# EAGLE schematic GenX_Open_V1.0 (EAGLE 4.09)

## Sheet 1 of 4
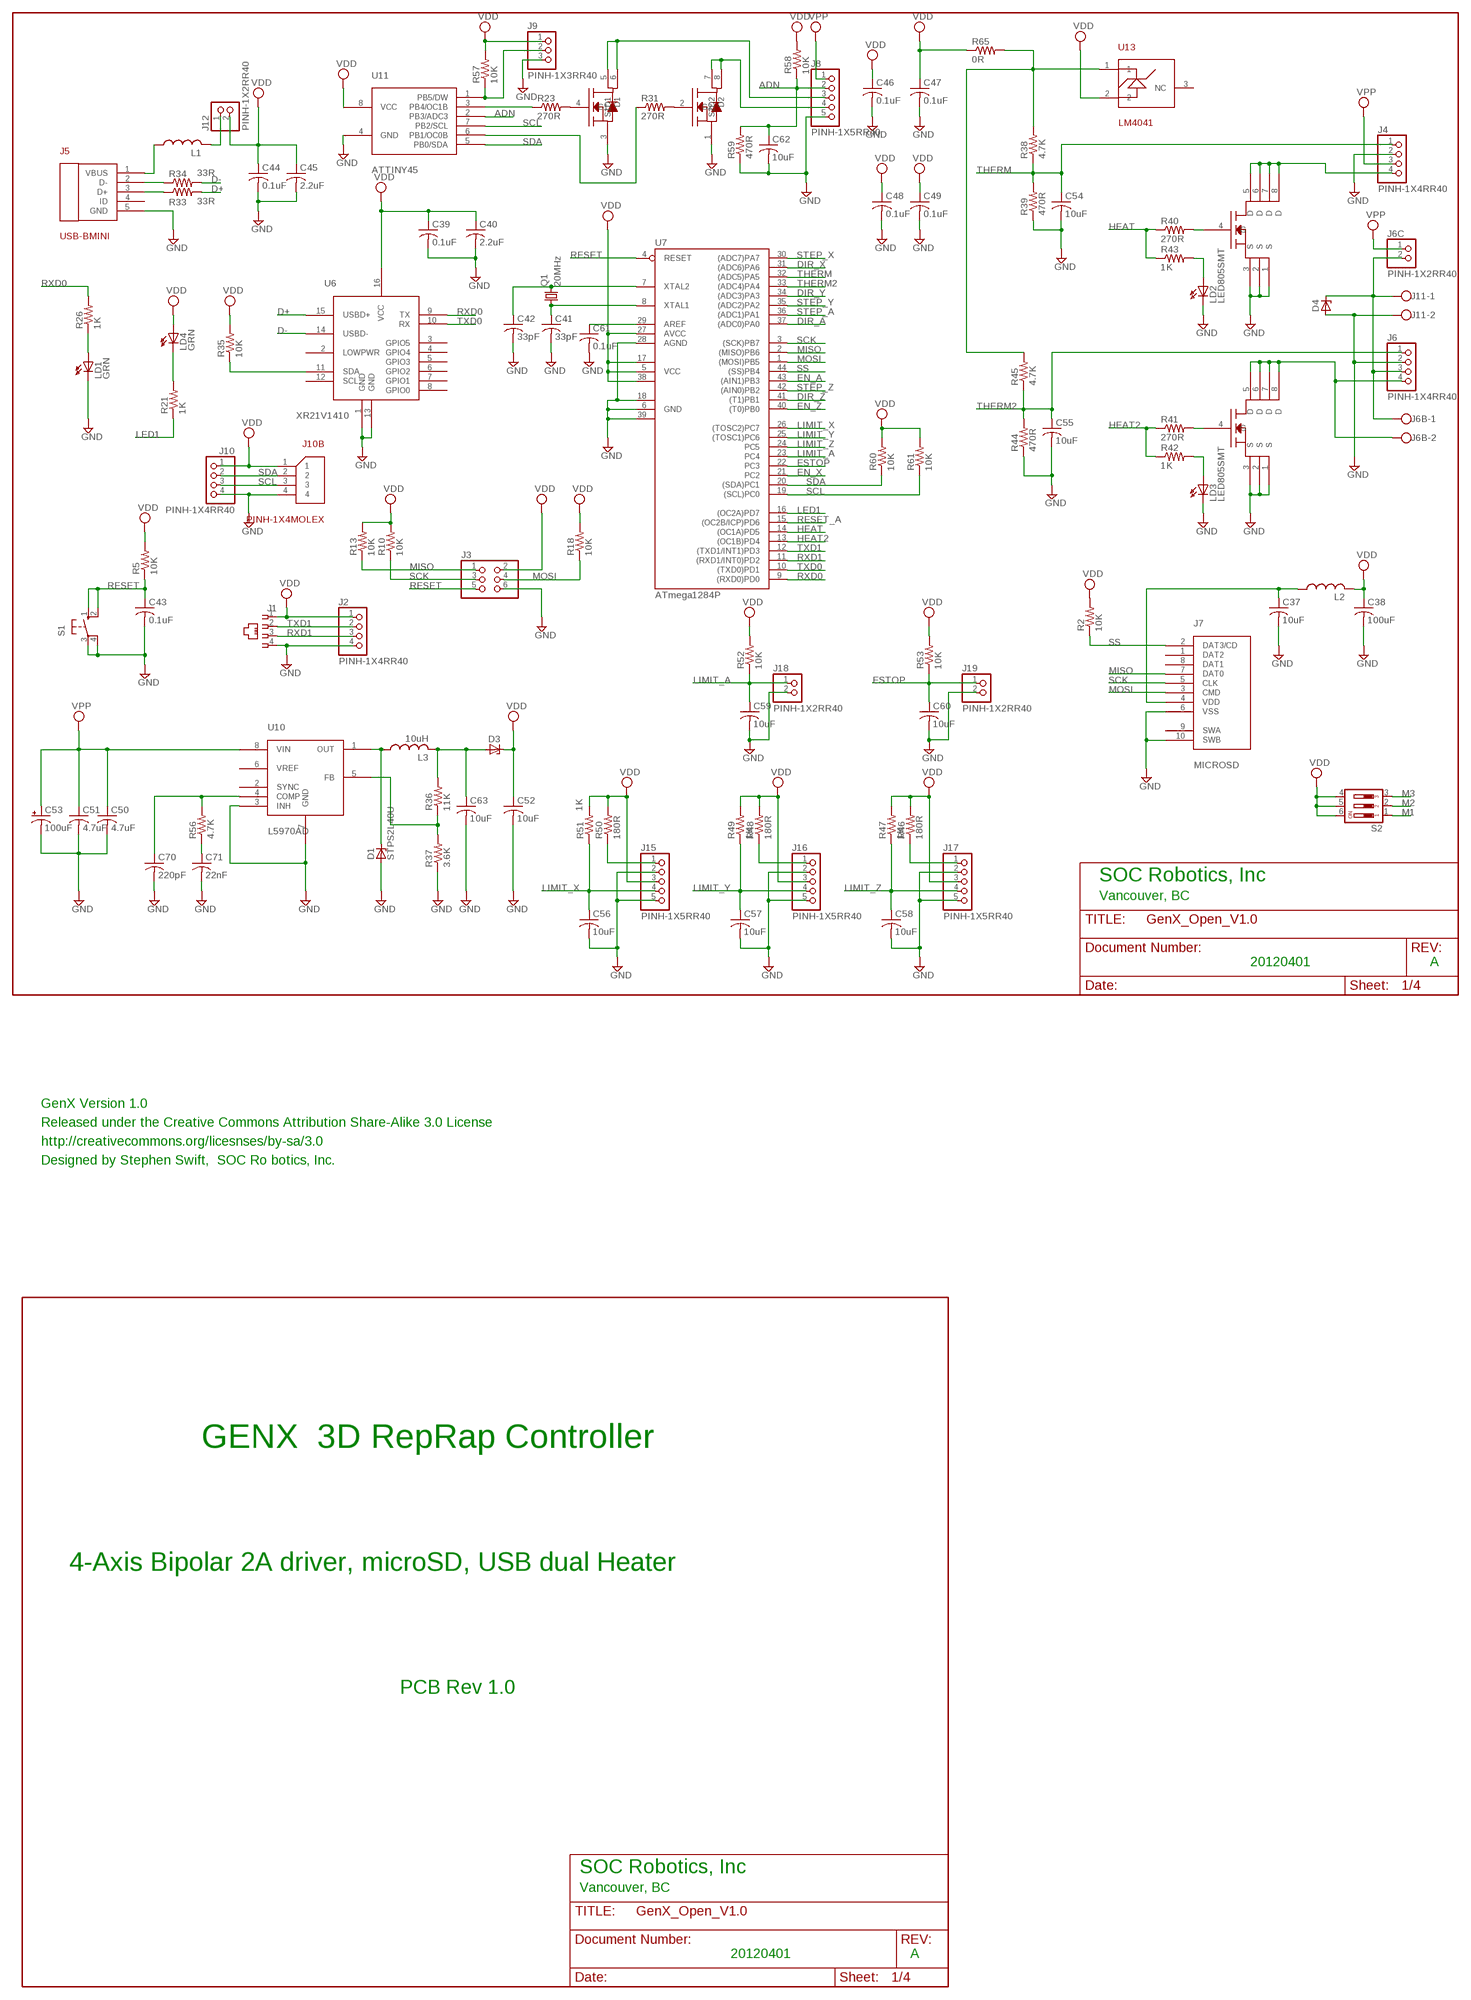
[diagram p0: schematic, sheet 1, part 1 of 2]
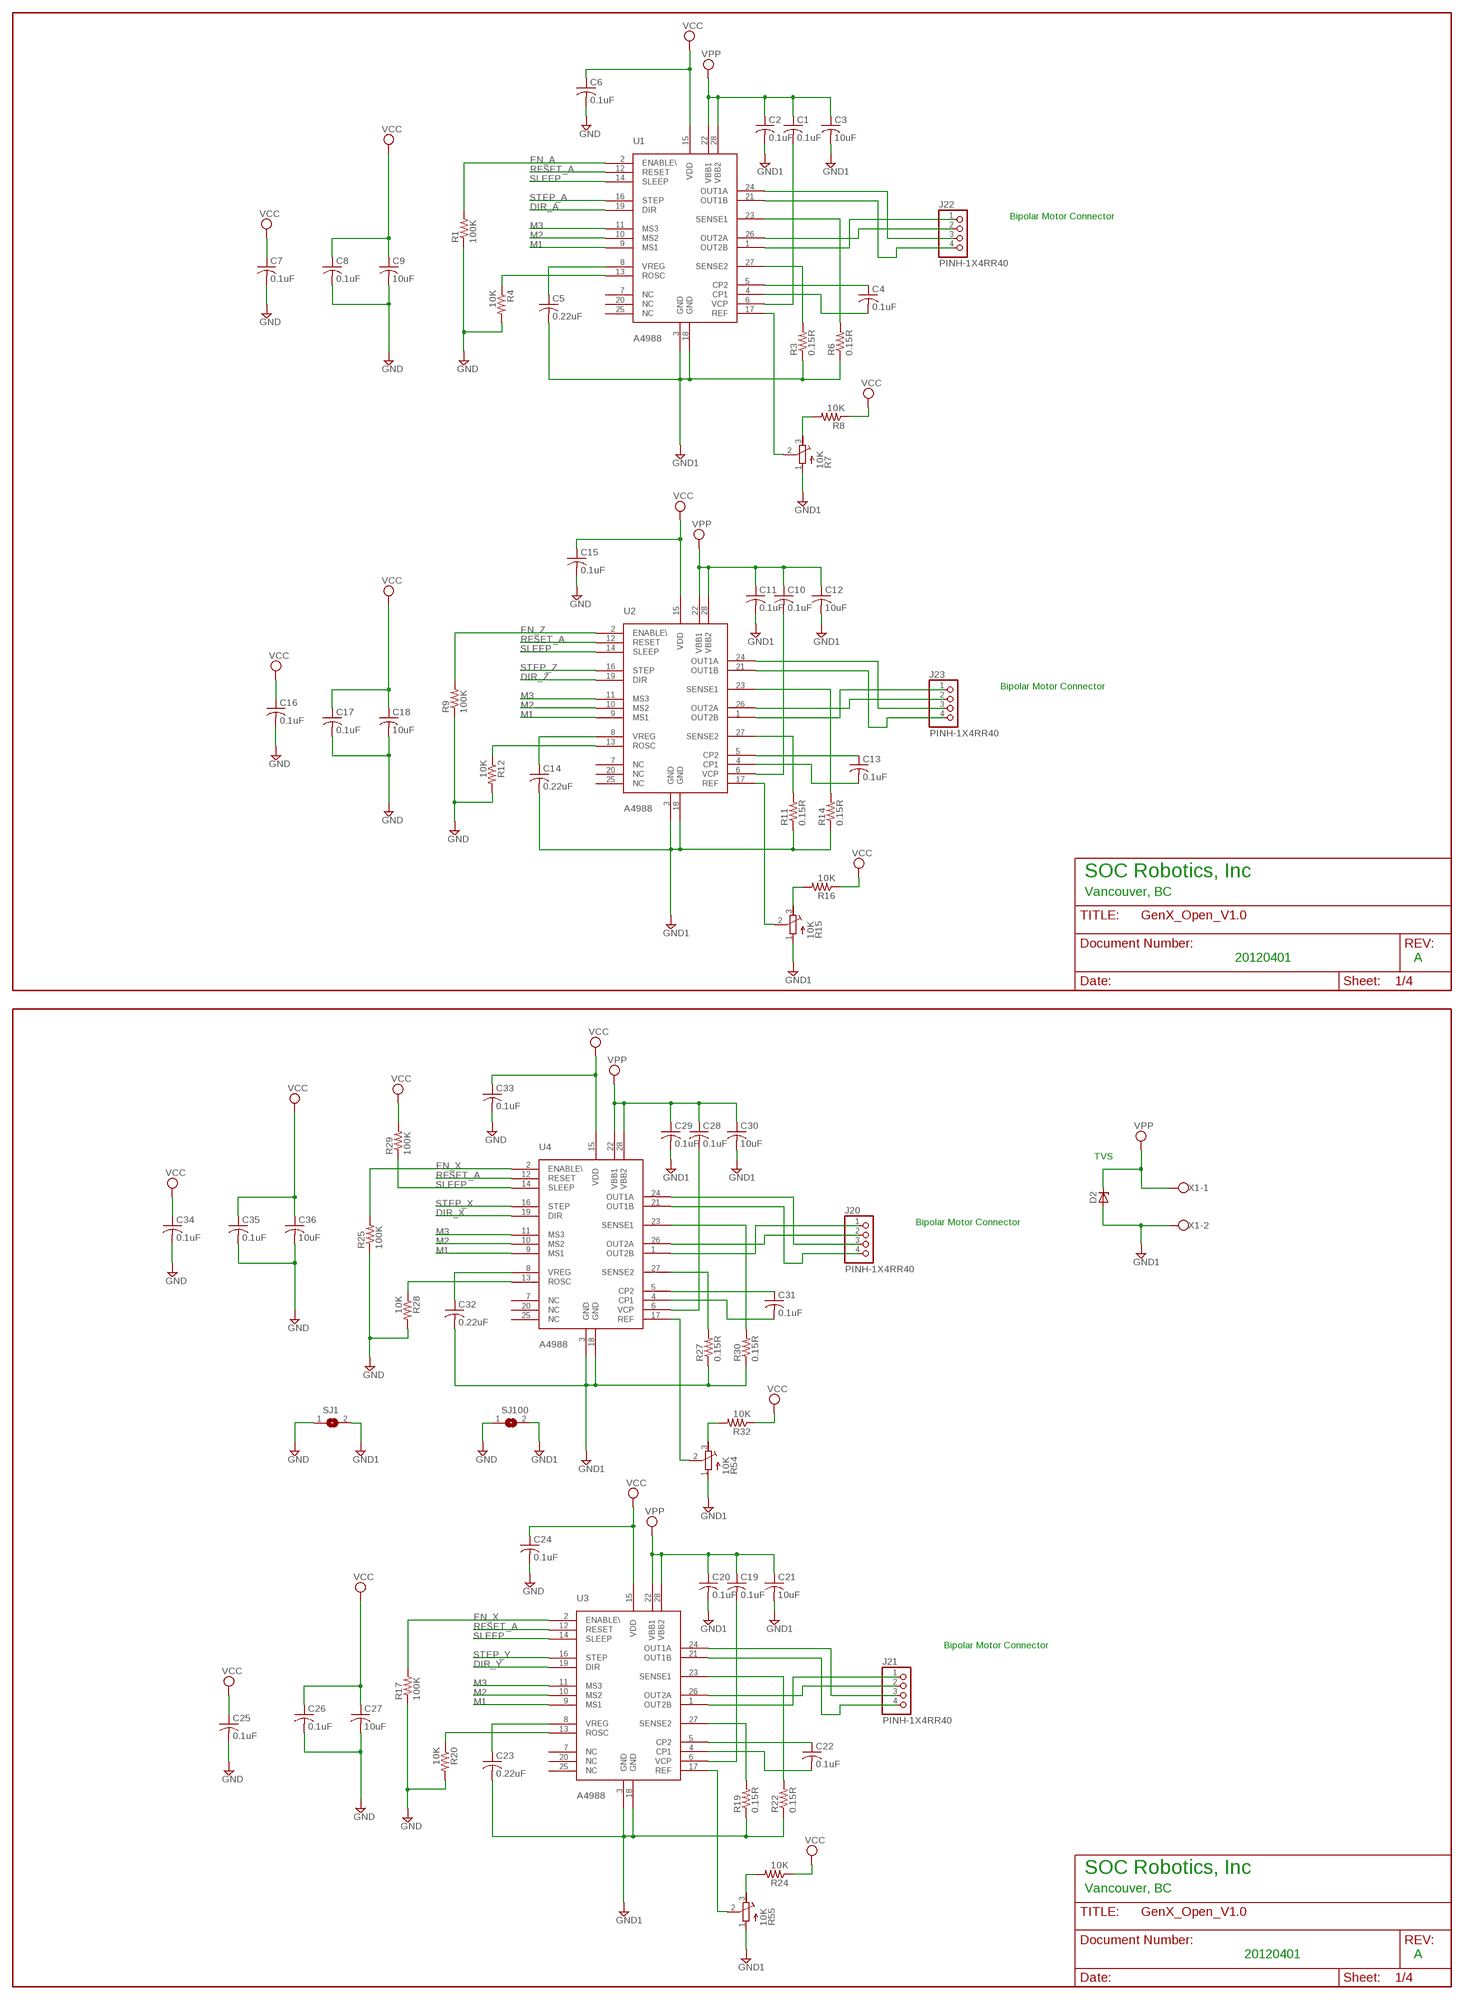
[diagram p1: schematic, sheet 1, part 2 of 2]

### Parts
C1  0.1uF  C-USC0603  [C0603]
C2  0.1uF  C-USC0805  [C0805]
C3  10uF  C-USC1210  [C1210]
C4  0.1uF  C-USC0603  [C0603]
C5  0.22uF  C-USC0603  [C0603]
C6  0.1uF  C-USC0603  [C0603]
C7  0.1uF  C-USC0805  [C0805]
C8  0.1uF  C-USC0603  [C0603]
C9  10uF  C-USC1206  [C1206]
C10  0.1uF  C-USC0603  [C0603]
C11  0.1uF  C-USC0805  [C0805]
C12  10uF  C-USC1210  [C1210]
C13  0.1uF  C-USC0603  [C0603]
C14  0.22uF  C-USC0603  [C0603]
C15  0.1uF  C-USC0603  [C0603]
C16  0.1uF  C-USC0805  [C0805]
C17  0.1uF  C-USC0603  [C0603]
C18  10uF  C-USC1206  [C1206]
C19  0.1uF  C-USC0603  [C0603]
C20  0.1uF  C-USC0805  [C0805]
C21  10uF  C-USC1210  [C1210]
C22  0.1uF  C-USC0603  [C0603]
C23  0.22uF  C-USC0603  [C0603]
C24  0.1uF  C-USC0603  [C0603]
C25  0.1uF  C-USC0805  [C0805]
C26  0.1uF  C-USC0603  [C0603]
C27  10uF  C-USC1206  [C1206]
C28  0.1uF  C-USC0603  [C0603]
C29  0.1uF  C-USC0805  [C0805]
C30  10uF  C-USC1210  [C1210]
C31  0.1uF  C-USC0603  [C0603]
C32  0.22uF  C-USC0603  [C0603]
C33  0.1uF  C-USC0603  [C0603]
C34  0.1uF  C-USC0805  [C0805]
C35  0.1uF  C-USC0603  [C0603]
C36  10uF  C-USC1206  [C1206]
C37  10uF  C-USC0805  [C0805]
C38  100uF  C-USC1206  [C1206]
C39  0.1uF  C-USC0805  [C0805]
C40  2.2uF  C-USC0805  [C0805]
C41  33pF  C-USC0805  [C0805]
C42  33pF  C-USC0805  [C0805]
C43  0.1uF  C-USC0805  [C0805]
C44  0.1uF  C-USC0805  [C0805]
C45  2.2uF  C-USC0805  [C0805]
C46  0.1uF  C-USC0805  [C0805]
C47  0.1uF  C-USC0805  [C0805]
C48  0.1uF  C-USC0805  [C0805]
C49  0.1uF  C-USC0805  [C0805]
C50  4.7uF  C-USC1206  [C1206]
C51  4.7uF  C-USC1206  [C1206]
C52  10uF  C-USC0805  [C0805]
C53  100uF  CPOL-USTAP5-60  [TAP5-60]
C54  10uF  C-USC0805  [C0805]
C55  10uF  C-USC0805  [C0805]
C56  10uF  C-USC0805  [C0805]
C57  10uF  C-USC0805  [C0805]
C58  10uF  C-USC0805  [C0805]
C59  10uF  C-USC0805  [C0805]
C60  10uF  C-USC0805  [C0805]
C61  0.1uF  C-USC0805  [C0805]
C62  10uF  C-USC0805  [C0805]
C63  10uF  C-USC0805  [C0805]
C70  220pF  C-USC0805  [C0805]
C71  22nF  C-USC0805  [C0805]
D1  STPS2L40U  ZENER-DIODESMB  [SMB]
D2  ZENER-DIODESMB  [SMB]
D3  ZENER-DIODESOD80C  [SOD80C]
D4  ZENER-DIODESMB  [SMB]
J1  520241-2  [520241-2]
J2  PINH-1X4RR40  [1X4ROUND]
J3  PINHD-2X3OCT  [2X03]
J4  PINH-1X4RR40  [1X4ROUND]
J5  USB-BMINI  [USB-BMINI]
J6  PINH-1X4RR40  [1X4ROUND]
J6B  AK300/2  [AK300/2]
J6C  PINH-1X2RR40  [1X2ROUND]
J7  MICROSD  [USD2]
J8  PINH-1X5RR40  [1X5ROUND]
J9  PINH-1X3RR40  [1X3ROUND]
J10  PINH-1X4RR40  [1X4ROUND]
J10B  PINH-1X4MOLEX  [1X4MOLEX]
J11  AK300/2  [AK300/2]
J12  PINH-1X2RR40  [1X2ROUND]
J15  PINH-1X5RR40  [1X5ROUND]
J16  PINH-1X5RR40  [1X5ROUND]
J17  PINH-1X5RR40  [1X5ROUND]
J18  PINH-1X2RR40  [1X2ROUND]
J19  PINH-1X2RR40  [1X2ROUND]
J20  PINH-1X4RR40  [1X4ROUND]
J21  PINH-1X4RR40  [1X4ROUND]
J22  PINH-1X4RR40  [1X4ROUND]
J23  PINH-1X4RR40  [1X4ROUND]
L1  L-USR0805  [R0805]
L2  L-USR0805  [R0805]
L3  10uH  L-USL4516C  [L4516C]
LD1  GRN  LED805SMT  [805SMT]
LD2  LED805SMT  [805SMT]
LD3  LED805SMT  [805SMT]
LD4  GRN  LED805SMT  [805SMT]
Q1  20MHz  ABM8  [ABM8]
R1  100K  R-US_R0603  [R0603]
R2  10K  R-US_R0805  [R0805]
R3  0.15R  R-US_R2010  [R2010]
R4  10K  R-US_R0603  [R0603]
R5  10K  R-US_R0805  [R0805]
R6  0.15R  R-US_R2010  [R2010]
R7  10K  R-TRIMM5W  [RTRIM5W]
R8  10K  R-US_R0603  [R0603]
R9  100K  R-US_R0603  [R0603]
R10  10K  R-US_R0805  [R0805]
R11  0.15R  R-US_R2010  [R2010]
R12  10K  R-US_R0603  [R0603]
R13  10K  R-US_R0805  [R0805]
R14  0.15R  R-US_R2010  [R2010]
R15  10K  R-TRIMM5W  [RTRIM5W]
R16  10K  R-US_R0603  [R0603]
R17  100K  R-US_R0603  [R0603]
R18  10K  R-US_R0805  [R0805]
R19  0.15R  R-US_R2010  [R2010]
R20  10K  R-US_R0603  [R0603]
R21  1K  R-US_R0805  [R0805]
R22  0.15R  R-US_R2010  [R2010]
R23  270R  R-US_R0805  [R0805]
R24  10K  R-US_R0603  [R0603]
R25  100K  R-US_R0603  [R0603]
R26  1K  R-US_R0805  [R0805]
R27  0.15R  R-US_R2010  [R2010]
R28  10K  R-US_R0603  [R0603]
R29  100K  R-US_R0603  [R0603]
R30  0.15R  R-US_R2010  [R2010]
R31  270R  R-US_R0805  [R0805]
R32  10K  R-US_R0603  [R0603]
R33  33R  R-US_R0603  [R0603]
R34  33R  R-US_R0603  [R0603]
R35  10K  R-US_R0805  [R0805]
R36  11K  R-US_R0805  [R0805]
R37  3.6K  R-US_R0805  [R0805]
R38  4.7K  R-US_R0805  [R0805]
R39  470R  R-US_R0805  [R0805]
R40  270R  R-US_R0805  [R0805]
R41  270R  R-US_R0805  [R0805]
R42  1K  R-US_R0805  [R0805]
R43  1K  R-US_R0805  [R0805]
R44  470R  R-US_R0805  [R0805]
R45  4.7K  R-US_R0805  [R0805]
R46  180R  R-US_R0805  [R0805]
R47  1K  R-US_R0805  [R0805]
R48  180R  R-US_R0805  [R0805]
R49  1K  R-US_R0805  [R0805]
R50  180R  R-US_R0805  [R0805]
R51  1K  R-US_R0805  [R0805]
R52  10K  R-US_R0805  [R0805]
R53  10K  R-US_R0805  [R0805]
R54  10K  R-TRIMM5W  [RTRIM5W]
R55  10K  R-TRIMM5W  [RTRIM5W]
R56  4.7K  R-US_R0805  [R0805]
R57  10K  R-US_R0805  [R0805]
R58  10K  R-US_R0805  [R0805]
R59  470R  R-US_R0805  [R0805]
R60  10K  R-US_R0805  [R0805]
R61  10K  R-US_R0805  [R0805]
R65  0R  R-US_R0603  [R0603]
S1  10-XXTHRU  [B3F-10XX]
S2  DIP03YL  [DIP03YL]
SJ1  SJS  [SJS]
SJ100  SJS  [SJS]
U1  A4988  [QFN28ET]
U2  A4988  [QFN28ET]
U3  A4988  [QFN28ET]
U4  A4988  [QFN28ET]
U6  XR21V1410  [QFN16-3]
U7  ATmega1284P  MEGA163A  [TQFP44]
U8  NDS9410A  [SO-8]
U9  NDS9410A  [SO-8]
U10  L5970AD  [SO8]
U11  ATTINY45  [SOIC-8]
U12  NDS9956A  [SO-8]
U13  LM4041  [SOT-23]
X1  AK300/2  [AK300/2]

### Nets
ADN: C62.1 J8.2 R58.1 R59.2 U11.2(PB3/ADC3)
D+: R33.2 U6.15(USBD+)
D-: R34.2 U6.14(USBD-)
DIR_A: U1.19(DIR) U7.37((ADC0)PA0)
DIR_X: U4.19(DIR) U7.31((ADC6)PA6)
DIR_Y: U3.19(DIR) U7.34((ADC3)PA3)
DIR_Z: U2.19(DIR) U7.41((T1)PB1)
EN_A: R1.2 U1.2(ENABLE\) U7.43((AIN1)PB3)
EN_X: R17.2 R25.2 U3.2(ENABLE\) U4.2(ENABLE\) U7.21(PC2)
EN_Z: R9.2 U2.2(ENABLE\) U7.40((T0)PB0)
ESTOP: C60.1 J19.1 R53.1 U7.22(PC3)
GND: C6.2 C7.2 C8.2 C9.2 C15.2 C16.2 C17.2 C18.2 C24.2 C25.2 C26.2 C27.2 C33.2 C34.2 C35.2 C36.2 C37.2 C38.2 C39.2 C40.2 C41.2 C42.2 C43.2 C44.2 C45.2 C46.2 C47.2 C48.2 C49.2 C50.2 C51.2 C52.2 C53.- C54.2 C55.2 C56.2 C57.2 C58.2 C59.2 C60.2 C61.2 C62.2 C63.2 C70.2 C71.2 D1.A D4.A J1.4 J2.4 J3.6 J4.2 J5.5(GND) J6.2 J7.6(VSS) J7.10(SWB) J8.5 J9.3 J10.4 J10B.4 J11.2 J15.2 J15.5 J16.2 J16.5 J17.2 J17.5 J18.2 J19.2 LD1.P$2(C) LD2.P$2(C) LD3.P$2(C) R1.1 R4.2 R9.1 R12.2 R17.1 R20.2 R25.1 R28.2 R37.1 R39.1 R44.1 R59.1 S1.3(P) S1.4(P1) SJ1.1 SJ100.1 U6.1(GND) U6.13(GND) U7.6(GND) U7.18(GND1) U7.28(AGND) U7.39(GND2) U8.1(S) U8.2(S) U8.3(S) U9.1(S) U9.2(S) U9.3(S) U10.3(INH) U10.7(GND) U11.4(GND) U12.1(S2) U12.3(S1)
GND1: C2.2 C3.2 C5.2 C11.2 C12.2 C14.2 C20.2 C21.2 C23.2 C29.2 C30.2 C32.2 D2.A R3.1 R6.1 R7.1(E) R11.1 R14.1 R15.1(E) R19.1 R22.1 R27.1 R30.1 R54.1(E) R55.1(E) SJ1.2 SJ100.2 U1.3(GND) U1.18(GND) U2.3(GND) U2.18(GND) U3.3(GND) U3.18(GND) U4.3(GND) U4.18(GND) X1.2
HEAT: R40.1 R43.1 U7.14((OC1A)PD5)
HEAT2: R41.1 R42.1 U7.13((OC1B)PD4)
LED1: R21.1 U7.16((OC2A)PD7)
LIMIT_A: C59.1 J18.1 R52.1 U7.23(PC4)
LIMIT_X: C56.1 J15.4 R51.1 U7.26((TOSC2)PC7)
LIMIT_Y: C57.1 J16.4 R49.1 U7.25((TOSC1)PC6)
LIMIT_Z: C58.1 J17.4 R47.1 U7.24(PC5)
M1: S2.1 U1.9(MS1) U2.9(MS1) U3.9(MS1) U4.9(MS1)
M2: S2.2 U1.10(MS2) U2.10(MS2) U3.10(MS2) U4.10(MS2)
M3: S2.3 U1.11(MS3) U2.11(MS3) U3.11(MS3) U4.11(MS3)
MISO: J3.1 J7.7(DAT0) R13.1 U7.2((MISO)PB6)
MOSI: J3.4 J7.3(CMD) R18.1 U7.1((MOSI)PB5)
N$1: R20.1 U3.13(ROSC)
N$1_A: R28.1 U4.13(ROSC)
N$1_B: R12.1 U2.13(ROSC)
N$1_B_C: R4.1 U1.13(ROSC)
N$2: J21.3 U3.24(OUT1A)
N$2_A: J20.3 U4.24(OUT1A)
N$2_B: J23.3 U2.24(OUT1A)
N$2_B_C: J22.3 U1.24(OUT1A)
N$3: J21.4 U3.21(OUT1B)
N$3_A: J20.4 U4.21(OUT1B)
N$3_B: J23.4 U2.21(OUT1B)
N$3_B_C: J22.4 U1.21(OUT1B)
N$4: J21.2 U3.26(OUT2A)
N$4_A: J20.2 U4.26(OUT2A)
N$4_B: J23.2 U2.26(OUT2A)
N$4_B_C: J22.2 U1.26(OUT2A)
N$5: J21.1 U3.1(OUT2B)
N$5_A: J20.1 U4.1(OUT2B)
N$5_B: J23.1 U2.1(OUT2B)
N$5_B_C: J22.1 U1.1(OUT2B)
N$6: C23.1 U3.8(VREG)
N$6_A: C32.1 U4.8(VREG)
N$6_B: C14.1 U2.8(VREG)
N$6_B_C: C5.1 U1.8(VREG)
N$9: J5.2(D-) R34.1
N$10: R22.2 U3.23(SENSE1)
N$10_A: R30.2 U4.23(SENSE1)
N$10_B: R14.2 U2.23(SENSE1)
N$10_B_C: R6.2 U1.23(SENSE1)
N$11: R19.2 U3.27(SENSE2)
N$11_A: R27.2 U4.27(SENSE2)
N$11_B: R11.2 U2.27(SENSE2)
N$11_B_C: R3.2 U1.27(SENSE2)
N$12: J5.3(D+) R33.1
N$13: J5.1(VBUS) L1.1
N$14: R23.2 U12.4(G1)
N$15: C42.1 Q1.3 U7.7(XTAL2)
N$16: C37.1 J7.4(VDD) L2.1
N$17: LD4.P$2(C) R21.2
N$18: R35.1 U6.11(SDA)
N$19: C22.1 U3.5(CP2)
N$19_A: C31.1 U4.5(CP2)
N$19_B: C13.1 U2.5(CP2)
N$19_B_C: C4.1 U1.5(CP2)
N$20: C22.2 U3.4(CP1)
N$20_A: C31.2 U4.4(CP1)
N$20_B: C13.2 U2.4(CP1)
N$20_B_C: C4.2 U1.4(CP1)
N$21: C19.2 U3.6(VCP)
N$21_A: C28.2 U4.6(VCP)
N$21_B: C10.2 U2.6(VCP)
N$21_B_C: C1.2 U1.6(VCP)
N$22: R36.1 R37.2 U10.5(FB)
N$23: R24.2 R55.3(A)
N$23_A: R32.2 R54.3(A)
N$23_B: R15.3(A) R16.2
N$23_B_C: R7.3(A) R8.2
N$24: R55.2(S) U3.17(REF)
N$24_A: R54.2(S) U4.17(REF)
N$24_B: R15.2(S) U2.17(REF)
N$24_B_C: R7.2(S) U1.17(REF)
N$25: LD1.P$1(A) R26.1
N$26: C70.1 R56.2 U10.4(COMP)
N$27: C71.1 R56.1
N$29: D1.C L3.1 U10.1(OUT)
N$30: J15.1 R50.1
N$31: LD2.P$1(A) R43.2
N$32: J6.4 J6B.2 U9.5(D) U9.6(D) U9.7(D) U9.8(D)
N$33: LD3.P$1(A) R42.2
N$34: J4.4 U8.5(D) U8.6(D) U8.7(D) U8.8(D)
N$35: R40.2 U8.4(G)
N$36: R41.2 U9.4(G)
N$37: J12.1 L1.2
N$38: C61.1 U7.29(AREF)
N$39: C63.1 D3.A L3.2 R36.2
N$40: R31.2 U12.2(G2)
N$41: J9.2 R57.1 U11.1(PB5/DW)
N$42: J8.3 U12.5(D1) U12.6(D1)
N$43: J8.4 U12.7(D2) U12.8(D2)
N$44: J16.1 R48.1
N$45: D4.C J6.3 J6B.1 J6C.2 J11.1
N$47: J17.1 R46.1
N$48: C41.1 Q1.1 U7.8(XTAL1)
N$49: R23.1 U11.3(PB4/OC1B)
N$51: R31.1 U11.6(PB1/OC0B)
N$55: R38.2 R45.2 R65.2 U13.1
RESET: C43.1 J3.5 R5.1 S1.1(S) S1.2(S1) U7.4(RESET)
RESET_A: U1.12(RESET) U2.12(RESET) U3.12(RESET) U4.12(RESET) U7.15((OC2B/ICP)PD6)
RXD0: R26.2 U6.9(TX) U7.9((RXD0)PD0)
RXD1: J1.3 J2.3 U7.11((RXD1/INT0)PD2)
SCK: J3.3 J7.5(CLK) R10.1 U7.3((SCK)PB7)
SCL: J10.3 J10B.3 R61.1 U7.19((SCL)PC0) U11.7(PB2/SCL)
SDA: J10.2 J10B.2 R60.1 U7.20((SDA)PC1) U11.5(PB0/SDA)
SLEEP: R29.1 U1.14(SLEEP) U2.14(SLEEP) U3.14(SLEEP) U4.14(SLEEP)
SS: J7.2(DAT3/CD) R2.1 U7.44((SS)PB4)
STEP_A: U1.16(STEP) U7.36((ADC1)PA1)
STEP_X: U4.16(STEP) U7.30((ADC7)PA7)
STEP_Y: U3.16(STEP) U7.35((ADC2)PA2)
STEP_Z: U2.16(STEP) U7.42((AIN0)PB2)
THERM: C54.1 J4.1 R38.1 R39.2 U7.32((ADC5)PA5)
THERM2: C55.1 J6.1 R44.2 R45.1 U7.33((ADC4)PA4)
TXD0: U6.10(RX) U7.10((TXD0)PD1)
TXD1: J1.2 J2.2 U7.12((TXD1/INT1)PD3)
VDD: C6.1 C7.1 C8.1 C9.1 C15.1 C16.1 C17.1 C18.1 C24.1 C25.1 C26.1 C27.1 C33.1 C34.1 C35.1 C36.1 C38.1 C39.1 C40.1 C44.1 C45.1 C46.1 C47.1 C48.1 C49.1 C52.1 D3.C J1.1 J2.1 J3.2 J9.1 J10.1 J10B.1 J12.2 J15.3 J16.3 J17.3 L2.2 LD4.P$1(A) R2.2 R5.2 R8.1 R10.2 R13.2 R16.1 R18.2 R24.1 R29.2 R32.1 R35.2 R46.2 R47.2 R48.2 R49.2 R50.2 R51.2 R52.2 R53.2 R57.2 R58.2 R60.2 R61.2 R65.1 S2.4 S2.5 S2.6 U1.15(VDD) U2.15(VDD) U3.15(VDD) U4.15(VDD) U6.16(VCC) U7.5(VCC) U7.17(VCC1) U7.27(AVCC) U7.38(VCC2) U11.8(VCC) U13.2 ; supply symbol labelled VCC
VPP: C1.1 C2.1 C3.1 C10.1 C11.1 C12.1 C19.1 C20.1 C21.1 C28.1 C29.1 C30.1 C50.1 C51.1 C53.+ D2.C J4.3 J6C.1 J8.1 U1.22(VBB1) U1.28(VBB2) U2.22(VBB1) U2.28(VBB2) U3.22(VBB1) U3.28(VBB2) U4.22(VBB1) U4.28(VBB2) U10.8(VIN) X1.1
Unconnected: J5.4(ID) J7.1(DAT2) J7.8(DAT1) J7.9(SWA) U1.7(NC) U1.20(NC) U1.25(NC) U2.7(NC) U2.20(NC) U2.25(NC) U3.7(NC) U3.20(NC) U3.25(NC) U4.7(NC) U4.20(NC) U4.25(NC) U6.2(LOWPWR) U6.3(GPIO5) U6.4(GPIO4) U6.5(GPIO3) U6.6(GPIO2) U6.7(GPIO1) U6.8(GPIO0) U6.12(SCL) U10.2(SYNC) U10.6(VREF) U13.3(NC)

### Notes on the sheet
- Bipolar Motor Connector
- Bipolar Motor Connector
- SOC Robotics, Inc
- SOC Robotics, Inc
- Vancouver, BC
- Vancouver, BC
- 20120401 | A
- 20120401 | A
- GenX Version 1.0
- Released under the Creative Commons Attribution Share-Alike 3.0 License
- http://creativecommons.org/licesnses/by-sa/3.0
- TVS
- Designed by Stephen Swift,  SOC Ro botics, Inc.
- Bipolar Motor Connector
- GENX  3D RepRap Controller
- 4-Axis Bipolar 2A driver, microSD, USB dual Heater
- Bipolar Motor Connector
- PCB Rev 1.0
- SOC Robotics, Inc | SOC Robotics, Inc
- Vancouver, BC | Vancouver, BC
- 20120401 | A | 20120401 | A

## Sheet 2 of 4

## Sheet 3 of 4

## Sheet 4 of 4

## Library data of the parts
C1-C52 C54-C63 C70 C71 = rcl:C-US: CAPACITOR, American symbol
C53 = rcl:CPOL-US: POLARIZED CAPACITOR, American symbol
D1-D4 = diode:ZENER-DIODE: Z-Diode
J1 = con-amp:520241-2: AMP CONNECTOR
J2 J4 J6 J10 J20-J23 = pinhead:PINH-1X4R: 1x4 Pin Head Round
J3 = pinhead:PINHD-2X3: PIN HEADER
J5 = con-TI DSK 2:USB-BMINI: USB Type B Mini Connector Male
J6B J11 X1 = con-ptr500:AK300/2: CONNECTOR
J6C J12 J18 J19 = pinhead:PINH-1X2R: 1x2 Pin head round
J7 = DSP-TI:MICROSD: microSD Connector
J8 J15-J17 = pinhead:PINH-1X5R: 1x5 Pin Head Round
J9 = pinhead:PINH-1X3R: 1x3 Pin Head Round
J10B = pinhead:PINH-1X4MOLEX: 1x4 Molex 1.25mm thru-hole
L1-L3 = rcl:L-US: INDUCTOR, American symbol
LD1-LD4 = led:LED805SMT: Surface Mount LED, 805 Size
Q1 = crystal:ABM8: Ultra small 3.2x2.5mm Crystal 3.5-60Mhz
R1-R6 R8-R14 R16-R53 R56-R61 R65 = rcl:R-US_: RESISTOR, American symbol
R7 R15 R54 R55 = rcl:R-TRIMM: Trimm resistor
S1 = switch-omron:10-XX: OMRON SWITCH
S2 = switch-dil:DIP03YL: DIL/CODE SWITCH
SJ1 SJ100 = jumper:SJ: SMD solder JUMPER
U1-U4 = DSP-TI:A4988: Microstepping controller 2A
U6 = DSP-TI:XR21V1410: USB 2.0 1Ch
U7 = atmel:MEGA163*: MICROCONTROLLER 16 Kbytes FLASH, 1 Kbytes EEPROM 1 Kbytes SRAM UART 8-channel 10 bit ADC hardware multiplier
U8 U9 = transistor-fet:NDS9410A: Single N-Channel Power MOSFET, 7.3A
U10 = v-reg:L5970AD: 1.5A Switching Regulator
U11 = atmel:ATTINY45: ATtiny processor 4K
U12 = transistor-fet:NDS9956A: Dual n-Channel Power MOSFET, 3.7A
U13 = DSP-TI:LM4041: Precision Voltage Referece 1.2V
